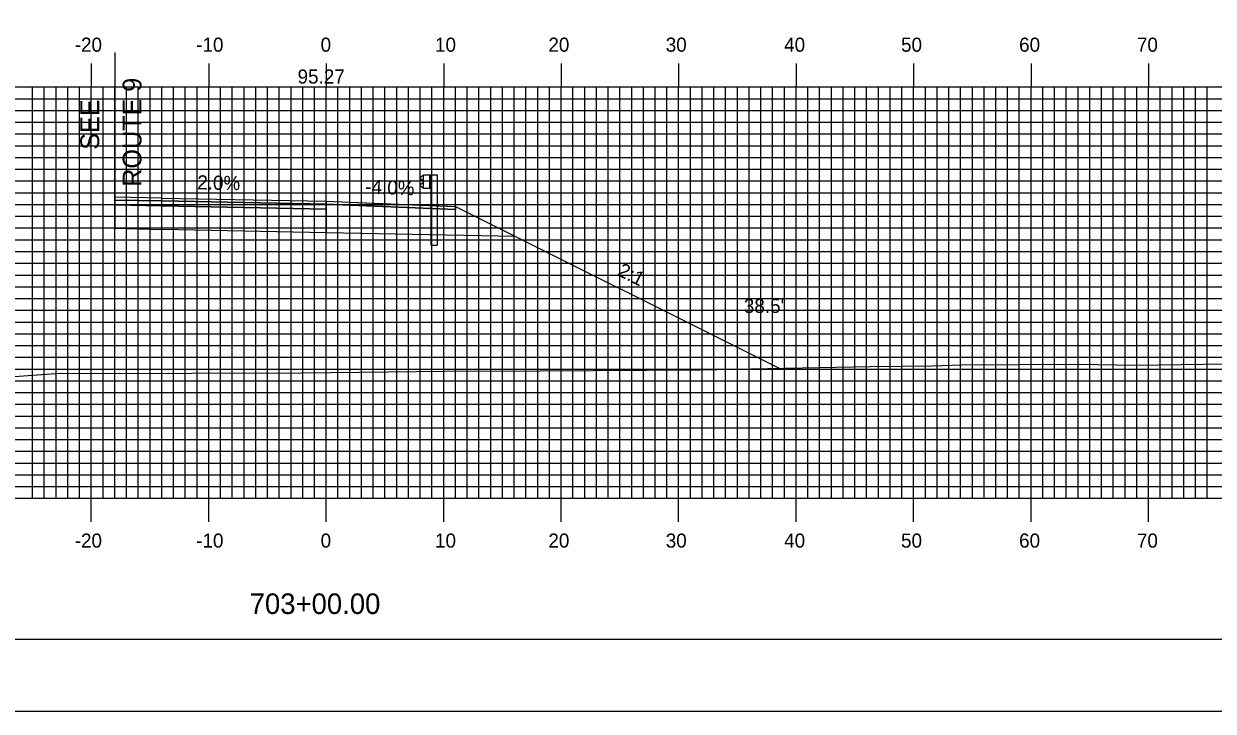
# Model space of a CAD drawing. Extents: x 853329 to 853673, y 364366 to 364586.
# Drawn here: x 853469.5 to 853570.7, y 364365.7 to 364424.2 of the extents above; entities that cross this region are included whole.
import ezdxf

# ---------------------------------------------------------------- set-up
doc = ezdxf.new("R2010")
doc.units = 0
for name, color, linetype in [('ANNOTATION', 7, 'Continuous'), ('BORDER', 7, 'Continuous'), ('D_Guardrail_Beam_Rt', 7, 'Continuous'), ('D_Roadway_Centerline_Text', 7, 'Continuous'), ('D_Roadway_Edge_Shoulder', 7, 'Continuous'), ('D_Roadway_Edge_TW', 7, 'Continuous'), ('D_Roadway_Pavement', 7, 'Continuous'), ('D_Roadway_SlopeLines', 7, 'Continuous'), ('D_Roadway_SubGrade', 7, 'Continuous'), ('D_Text_Standard', 7, 'Continuous'), ('H_V ANNOTATION', 7, 'Continuous'), ('MAJOR', 7, 'Continuous'), ('MINOR', 7, 'Continuous'), ('PLOT BOUNDARY', 7, 'Continuous'), ('S_Roadway_Centerline', 7, 'Continuous')]:
    doc.layers.add(name, color=color, linetype=linetype)

msp = doc.modelspace()

# ---------------------------------------------------------------- linework, layer by layer
at = {"layer": 'BORDER'}
msp.add_lwpolyline([(853345.6, 364371.79), (853665.6, 364371.79), (853665.6, 364581.79), (853345.6, 364581.79)], close=True, dxfattribs=at)
at = {"layer": 'D_Guardrail_Beam_Rt'}
for p, q in [((853503.39, 364411.22), (853503.24, 364411.12)), ((853503.24, 364410.97), (853503.44, 364410.84)), ((853503.48, 364411.24), (853503.4, 364411.22)), ((853503.48, 364411.32), (853504.16, 364411.32)), ((853503.48, 364410.16), (853503.48, 364411.32)), ((853504, 364411.32), (853504, 364410.16)), ((853504.1, 364411.32), (853504.1, 364410.16)), ((853504.16, 364411.32), (853504.63, 364411.32)), ((853504.16, 364411.32), (853504.16, 364410.16)), ((853504.63, 364411.32), (853504.63, 364405.32)), ((853503.44, 364410.64), (853503.24, 364410.5)), ((853503.24, 364410.36), (853503.39, 364410.26)), ((853503.4, 364410.25), (853503.48, 364410.24)), ((853503.47, 364410.77), (853503.47, 364410.7)), ((853504.16, 364410.16), (853503.48, 364410.16)), ((853504.14, 364405.32), (853504.14, 364410.16)), ((853504.14, 364405.32), (853504.63, 364405.32))]:
    msp.add_line(p, q, dxfattribs=at)
for centre, major_axis, start_param, end_param in [((853503.29, 364411.05), (-0.0877, 0), 5.323254, 7.243116), ((853503.41, 364411.18), (-0.0417, 0), 4.907132, 5.323254), ((853503.29, 364410.43), (-0.0877, 0), 5.323254, 7.243116), ((853503.41, 364410.29), (-0.0417, 0), 0.959931, 1.376053), ((853503.39, 364410.77), (0.0789, 0), 0, 0.959931), ((853503.39, 364410.7), (0.0789, 0), 5.323254, 6.283185)]:
    msp.add_ellipse(centre, major_axis=major_axis, ratio=0.995501, start_param=start_param, end_param=end_param, dxfattribs=at)
at = {"layer": 'D_Roadway_Edge_Shoulder'}
for points in [[(853481.2, 364409.34), (853477.2, 364409.42), (853477.2, 364409.17), (853481.2, 364409.09)], [(853481.2, 364409.34), (853477.2, 364409.42), (853477.2, 364409.17), (853481.2, 364409.09)], [(853495.2, 364409.06), (853503.2, 364408.74), (853503.2, 364408.74), (853506.2, 364408.62), (853506.2, 364408.37), (853495.2, 364408.81)], [(853495.2, 364409.06), (853506.2, 364408.62), (853506.2, 364408.37), (853495.2, 364408.81)], [(853495.2, 364409.06), (853503.2, 364408.74), (853503.2, 364408.74), (853506.2, 364408.62), (853506.2, 364408.37), (853495.2, 364408.81)]]:
    msp.add_lwpolyline(points, close=True, dxfattribs=at)
at = {"layer": 'D_Roadway_Edge_TW'}
msp.add_lwpolyline([(853481.2, 364409.34), (853495.2, 364409.06), (853495.2, 364408.81), (853481.2, 364409.09)], close=True, dxfattribs=at)
msp.add_lwpolyline([(853481.2, 364409.34), (853495.2, 364409.06), (853495.2, 364408.81), (853481.2, 364409.09)], close=True, dxfattribs=at)
msp.add_lwpolyline([(853481.2, 364409.34), (853495.2, 364409.06), (853495.2, 364408.81), (853481.2, 364409.09)], close=True, dxfattribs=at)
msp.add_lwpolyline([(853481.2, 364409.34), (853495.2, 364409.06), (853495.2, 364408.81), (853481.2, 364409.09)], close=True, dxfattribs=at)
at = {"layer": 'D_Roadway_Pavement'}
for points in [[(853481.2, 364409.09), (853477.2, 364409.17), (853477.2, 364408.75), (853481.2, 364408.67)], [(853481.2, 364409.09), (853477.2, 364409.17), (853477.2, 364408.75), (853481.2, 364408.67)], [(853481.2, 364409.09), (853495.2, 364408.81), (853495.2, 364408.39), (853481.2, 364408.67)], [(853481.2, 364409.09), (853495.2, 364408.81), (853495.2, 364408.39), (853481.2, 364408.67)], [(853481.2, 364409.09), (853495.2, 364408.81), (853495.2, 364408.39), (853481.2, 364408.67)], [(853481.2, 364409.09), (853495.2, 364408.81), (853495.2, 364408.39), (853481.2, 364408.67)]]:
    msp.add_lwpolyline(points, close=True, dxfattribs=at)
msp.add_lwpolyline([(853495.2, 364408.81), (853495.2, 364408.39)], dxfattribs=at)
msp.add_lwpolyline([(853495.2, 364408.81), (853495.2, 364408.39)], dxfattribs=at)
msp.add_lwpolyline([(853495.2, 364408.81), (853495.2, 364408.39)], dxfattribs=at)
msp.add_lwpolyline([(853495.2, 364408.81), (853495.2, 364408.39)], dxfattribs=at)
msp.add_lwpolyline([(853495.2, 364408.81), (853495.2, 364408.39)], dxfattribs=at)
msp.add_lwpolyline([(853495.2, 364408.81), (853495.2, 364408.39)], dxfattribs=at)
msp.add_lwpolyline([(853495.2, 364408.81), (853495.2, 364408.39)], dxfattribs=at)
msp.add_lwpolyline([(853495.2, 364408.81), (853495.2, 364408.39)], dxfattribs=at)
msp.add_lwpolyline([(853495.2, 364408.81), (853495.2, 364408.39)], dxfattribs=at)
msp.add_lwpolyline([(853495.2, 364408.81), (853495.2, 364408.39)], dxfattribs=at)
msp.add_lwpolyline([(853495.2, 364408.81), (853495.2, 364408.39)], dxfattribs=at)
msp.add_lwpolyline([(853495.2, 364408.81), (853495.2, 364408.39)], dxfattribs=at)
msp.add_lwpolyline([(853495.2, 364408.81), (853495.2, 364408.39)], dxfattribs=at)
msp.add_lwpolyline([(853495.2, 364408.81), (853495.2, 364408.39)], dxfattribs=at)
at = {"layer": 'D_Roadway_SlopeLines'}
msp.add_lwpolyline([(853506.2, 364408.62), (853533.75, 364394.85)], dxfattribs=at)
msp.add_lwpolyline([(853506.2, 364408.62), (853533.75, 364394.85)], dxfattribs=at)
at = {"layer": 'D_Roadway_SubGrade'}
msp.add_line((853477.2, 364421.72), (853477.2, 364406.77), dxfattribs=at)
for points in [[(853481.2, 364408.67), (853477.2, 364408.75), (853477.2, 364409.17), (853477.2, 364406.77), (853481.2, 364406.67)], [(853481.2, 364408.67), (853495.2, 364408.39), (853495.2, 364406.39), (853481.2, 364406.67)], [(853481.2, 364408.67), (853495.2, 364408.39), (853495.2, 364406.39), (853481.2, 364406.67)], [(853481.2, 364408.67), (853495.2, 364408.39), (853495.2, 364406.39), (853481.2, 364406.67)], [(853481.2, 364408.67), (853495.2, 364408.39), (853495.2, 364406.39), (853481.2, 364406.67)], [(853495.2, 364408.39), (853495.2, 364408.81), (853506.2, 364408.37), (853506.2, 364408.62), (853511.3, 364406.07), (853495.2, 364406.39)], [(853495.2, 364408.39), (853495.2, 364408.81), (853506.2, 364408.37), (853506.2, 364408.62), (853511.3, 364406.07), (853495.2, 364406.39)]]:
    msp.add_lwpolyline(points, close=True, dxfattribs=at)
at = {"layer": 'MAJOR'}
for p, q in [((853475.2, 364420.79), (853475.2, 364418.79)), ((853485.2, 364420.79), (853485.2, 364418.79)), ((853495.2, 364420.79), (853495.2, 364418.79)), ((853505.2, 364420.79), (853505.2, 364418.79)), ((853515.2, 364420.79), (853515.2, 364418.79)), ((853525.2, 364420.79), (853525.2, 364418.79)), ((853535.2, 364420.79), (853535.2, 364418.79)), ((853545.2, 364420.79), (853545.2, 364418.79)), ((853555.2, 364420.79), (853555.2, 364418.79)), ((853565.2, 364420.79), (853565.2, 364418.79)), ((853355.2, 364418.79), (853635.2, 364418.79)), ((853355.2, 364418.79), (853635.2, 364418.79)), ((853475.2, 364383.79), (853475.2, 364418.79)), ((853485.2, 364383.79), (853485.2, 364418.79)), ((853495.2, 364383.79), (853495.2, 364418.79)), ((853505.2, 364383.79), (853505.2, 364418.79)), ((853515.2, 364383.79), (853515.2, 364418.79)), ((853525.2, 364383.79), (853525.2, 364418.79)), ((853535.2, 364383.79), (853535.2, 364418.79)), ((853545.2, 364383.79), (853545.2, 364418.79)), ((853555.2, 364383.79), (853555.2, 364418.79)), ((853565.2, 364383.79), (853565.2, 364418.79)), ((853355.2, 364413.79), (853635.2, 364413.79)), ((853355.2, 364408.79), (853635.2, 364408.79)), ((853355.2, 364403.79), (853635.2, 364403.79)), ((853355.2, 364398.79), (853635.2, 364398.79)), ((853355.2, 364393.79), (853635.2, 364393.79)), ((853355.2, 364388.79), (853635.2, 364388.79)), ((853355.2, 364383.79), (853635.2, 364383.79)), ((853355.2, 364383.79), (853635.2, 364383.79)), ((853475.2, 364381.78), (853475.2, 364383.79)), ((853485.2, 364381.78), (853485.2, 364383.79)), ((853495.2, 364381.78), (853495.2, 364383.79)), ((853505.2, 364381.78), (853505.2, 364383.79)), ((853515.2, 364381.78), (853515.2, 364383.79)), ((853525.2, 364381.78), (853525.2, 364383.79)), ((853535.2, 364381.78), (853535.2, 364383.79)), ((853545.2, 364381.78), (853545.2, 364383.79)), ((853555.2, 364381.78), (853555.2, 364383.79)), ((853565.2, 364381.78), (853565.2, 364383.79))]:
    msp.add_line(p, q, dxfattribs=at)
at = {"layer": 'MINOR'}
for p, q in [((853470.2, 364383.79), (853470.2, 364418.79)), ((853471.2, 364383.79), (853471.2, 364418.79)), ((853472.2, 364383.79), (853472.2, 364418.79)), ((853473.2, 364383.79), (853473.2, 364418.79)), ((853474.2, 364383.79), (853474.2, 364418.79)), ((853476.2, 364383.79), (853476.2, 364418.79)), ((853477.2, 364383.79), (853477.2, 364418.79)), ((853478.2, 364383.79), (853478.2, 364418.79)), ((853479.2, 364383.79), (853479.2, 364418.79)), ((853480.2, 364383.79), (853480.2, 364418.79)), ((853481.2, 364383.79), (853481.2, 364418.79)), ((853482.2, 364383.79), (853482.2, 364418.79)), ((853483.2, 364383.79), (853483.2, 364418.79)), ((853484.2, 364383.79), (853484.2, 364418.79)), ((853486.2, 364383.79), (853486.2, 364418.79)), ((853487.2, 364383.79), (853487.2, 364418.79)), ((853488.2, 364383.79), (853488.2, 364418.79)), ((853489.2, 364383.79), (853489.2, 364418.79)), ((853490.2, 364383.79), (853490.2, 364418.79)), ((853491.2, 364383.79), (853491.2, 364418.79)), ((853492.2, 364383.79), (853492.2, 364418.79)), ((853493.2, 364383.79), (853493.2, 364418.79)), ((853494.2, 364383.79), (853494.2, 364418.79)), ((853496.2, 364383.79), (853496.2, 364418.79)), ((853497.2, 364383.79), (853497.2, 364418.79)), ((853498.2, 364383.79), (853498.2, 364418.79)), ((853499.2, 364383.79), (853499.2, 364418.79)), ((853500.2, 364383.79), (853500.2, 364418.79)), ((853501.2, 364383.79), (853501.2, 364418.79)), ((853502.2, 364383.79), (853502.2, 364418.79)), ((853503.2, 364383.79), (853503.2, 364418.79)), ((853504.2, 364383.79), (853504.2, 364418.79)), ((853506.2, 364383.79), (853506.2, 364418.79)), ((853507.2, 364383.79), (853507.2, 364418.79)), ((853508.2, 364383.79), (853508.2, 364418.79)), ((853509.2, 364383.79), (853509.2, 364418.79)), ((853510.2, 364383.79), (853510.2, 364418.79)), ((853511.2, 364383.79), (853511.2, 364418.79)), ((853512.2, 364383.79), (853512.2, 364418.79)), ((853513.2, 364383.79), (853513.2, 364418.79)), ((853514.2, 364383.79), (853514.2, 364418.79)), ((853516.2, 364383.79), (853516.2, 364418.79)), ((853517.2, 364383.79), (853517.2, 364418.79)), ((853518.2, 364383.79), (853518.2, 364418.79)), ((853519.2, 364383.79), (853519.2, 364418.79)), ((853520.2, 364383.79), (853520.2, 364418.79)), ((853521.2, 364383.79), (853521.2, 364418.79)), ((853522.2, 364383.79), (853522.2, 364418.79)), ((853523.2, 364383.79), (853523.2, 364418.79)), ((853524.2, 364383.79), (853524.2, 364418.79)), ((853526.2, 364383.79), (853526.2, 364418.79)), ((853527.2, 364383.79), (853527.2, 364418.79)), ((853528.2, 364383.79), (853528.2, 364418.79)), ((853529.2, 364383.79), (853529.2, 364418.79)), ((853530.2, 364383.79), (853530.2, 364418.79)), ((853531.2, 364383.79), (853531.2, 364418.79)), ((853532.2, 364383.79), (853532.2, 364418.79)), ((853533.2, 364383.79), (853533.2, 364418.79)), ((853534.2, 364383.79), (853534.2, 364418.79)), ((853536.2, 364383.79), (853536.2, 364418.79)), ((853537.2, 364383.79), (853537.2, 364418.79)), ((853538.2, 364383.79), (853538.2, 364418.79)), ((853539.2, 364383.79), (853539.2, 364418.79)), ((853540.2, 364383.79), (853540.2, 364418.79)), ((853541.2, 364383.79), (853541.2, 364418.79)), ((853542.2, 364383.79), (853542.2, 364418.79)), ((853543.2, 364383.79), (853543.2, 364418.79)), ((853544.2, 364383.79), (853544.2, 364418.79)), ((853546.2, 364383.79), (853546.2, 364418.79)), ((853547.2, 364383.79), (853547.2, 364418.79)), ((853548.2, 364383.79), (853548.2, 364418.79)), ((853549.2, 364383.79), (853549.2, 364418.79)), ((853550.2, 364383.79), (853550.2, 364418.79)), ((853551.2, 364383.79), (853551.2, 364418.79)), ((853552.2, 364383.79), (853552.2, 364418.79)), ((853553.2, 364383.79), (853553.2, 364418.79)), ((853554.2, 364383.79), (853554.2, 364418.79)), ((853556.2, 364383.79), (853556.2, 364418.79)), ((853557.2, 364383.79), (853557.2, 364418.79)), ((853558.2, 364383.79), (853558.2, 364418.79)), ((853559.2, 364383.79), (853559.2, 364418.79)), ((853560.2, 364383.79), (853560.2, 364418.79)), ((853561.2, 364383.79), (853561.2, 364418.79)), ((853562.2, 364383.79), (853562.2, 364418.79)), ((853563.2, 364383.79), (853563.2, 364418.79)), ((853564.2, 364383.79), (853564.2, 364418.79)), ((853566.2, 364383.79), (853566.2, 364418.79)), ((853567.2, 364383.79), (853567.2, 364418.79)), ((853568.2, 364383.79), (853568.2, 364418.79)), ((853569.2, 364383.79), (853569.2, 364418.79)), ((853570.2, 364383.79), (853570.2, 364418.79)), ((853355.2, 364417.79), (853635.2, 364417.79)), ((853355.2, 364416.79), (853635.2, 364416.79)), ((853355.2, 364415.79), (853635.2, 364415.79)), ((853355.2, 364414.79), (853635.2, 364414.79)), ((853355.2, 364412.79), (853635.2, 364412.79)), ((853355.2, 364411.79), (853635.2, 364411.79)), ((853355.2, 364410.79), (853635.2, 364410.79)), ((853355.2, 364409.79), (853635.2, 364409.79)), ((853355.2, 364407.79), (853635.2, 364407.79)), ((853355.2, 364406.79), (853635.2, 364406.79)), ((853355.2, 364405.79), (853635.2, 364405.79)), ((853355.2, 364404.79), (853635.2, 364404.79)), ((853355.2, 364402.79), (853635.2, 364402.79)), ((853355.2, 364401.79), (853635.2, 364401.79)), ((853355.2, 364400.79), (853635.2, 364400.79)), ((853355.2, 364399.79), (853635.2, 364399.79)), ((853355.2, 364397.79), (853635.2, 364397.79)), ((853355.2, 364396.79), (853635.2, 364396.79)), ((853355.2, 364395.79), (853635.2, 364395.79)), ((853355.2, 364394.79), (853635.2, 364394.79)), ((853355.2, 364392.79), (853635.2, 364392.79)), ((853355.2, 364391.79), (853635.2, 364391.79)), ((853355.2, 364390.79), (853635.2, 364390.79)), ((853355.2, 364389.79), (853635.2, 364389.79)), ((853355.2, 364387.79), (853635.2, 364387.79)), ((853355.2, 364386.79), (853635.2, 364386.79)), ((853355.2, 364385.79), (853635.2, 364385.79)), ((853355.2, 364384.79), (853635.2, 364384.79))]:
    msp.add_line(p, q, dxfattribs=at)
at = {"layer": 'PLOT BOUNDARY'}
msp.add_lwpolyline([(853329.42, 364365.67), (853669.42, 364365.67), (853669.42, 364585.67), (853329.42, 364585.67)], close=True, dxfattribs=at)
at = {"layer": 'S_Roadway_Centerline'}
msp.add_lwpolyline([(853461.87, 364393.67), (853472.58, 364394.44), (853474.39, 364394.4), (853493.12, 364394.47), (853507.75, 364394.63), (853510.68, 364394.6), (853513.41, 364394.63), (853526.99, 364394.71), (853541.49, 364395), (853546.8, 364395.05), (853549.27, 364395.15), (853559.15, 364395.19), (853564.15, 364395.13), (853571.8, 364395.22), (853580.87, 364395.97), (853582.99, 364396.12), (853600.33, 364396.12), (853608.66, 364396.07), (853619.34, 364395.61), (853625.11, 364395.29), (853635.2, 364394.92)], dxfattribs=at)

# ---------------------------------------------------------------- texts
at = {"layer": 'ANNOTATION'}
for s, height, rotation, p in [('ROUTE 9', 1.6, 90, (853479.47, 364410.3)), ('SEE', 1.6, 90, (853475.87, 364413.45)), ('2.0%', 1.2, 358.8542, (853484.21, 364410.08)), ('-4.0%', 1.2, 357.7094, (853498.5, 364409.73)), ('2:1', 1.2, 333.4349, (853519.91, 364402.8))]:
    msp.add_text(s, height=height, rotation=rotation, dxfattribs=at).set_placement(p)
at = {"layer": 'D_Roadway_Centerline_Text'}
msp.add_text('95.27', height=1.2, dxfattribs=at).set_placement((853492.76, 364419.08))
at = {"layer": 'D_Text_Standard'}
msp.add_text("38.5'", height=1.2, dxfattribs=at).set_placement((853530.75, 364399.56))
at = {"layer": 'H_V ANNOTATION'}
for s, height, p in [('-20', 1.2, (853473.79, 364421.79)), ('-10', 1.2, (853484.13, 364421.79)), ('0', 1.2, (853494.72, 364421.79)), ('10', 1.2, (853504.46, 364421.79)), ('20', 1.2, (853514.11, 364421.79)), ('30', 1.2, (853524.1, 364421.79)), ('40', 1.2, (853534.18, 364421.79)), ('50', 1.2, (853544.13, 364421.79)), ('60', 1.2, (853554.18, 364421.79)), ('70', 1.2, (853564.21, 364421.79)), ('-20', 1.2, (853473.79, 364379.59)), ('-10', 1.2, (853484.13, 364379.59)), ('0', 1.2, (853494.72, 364379.59)), ('10', 1.2, (853504.46, 364379.59)), ('20', 1.2, (853514.11, 364379.59)), ('30', 1.2, (853524.1, 364379.59)), ('40', 1.2, (853534.18, 364379.59)), ('50', 1.2, (853544.13, 364379.59)), ('60', 1.2, (853554.18, 364379.59)), ('70', 1.2, (853564.21, 364379.59)), ('703+00.00', 1.75, (853488.68, 364373.94))]:
    msp.add_text(s, height=height, dxfattribs=at).set_placement(p)

doc.saveas('drawing.dxf')
